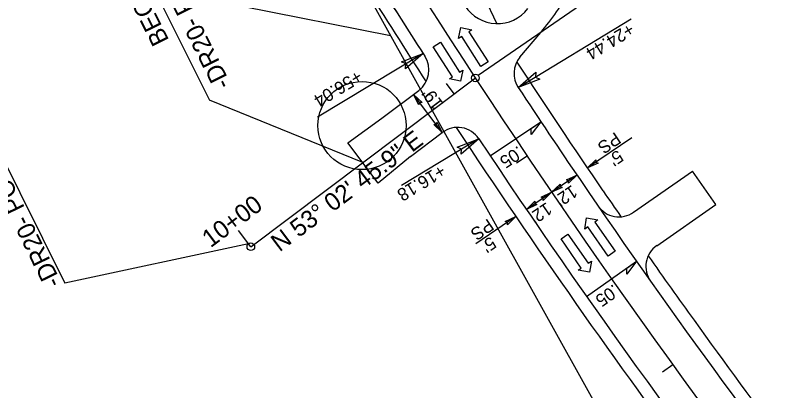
# Model space of a CAD drawing. Extents: x 472216 to 481979, y 489069 to 507339.
# Drawn here: x 476040.5 to 476343.7, y 501112.8 to 501260.2 of the extents above; entities that cross this region are included whole.
import ezdxf

# ---------------------------------------------------------------- set-up
doc = ezdxf.new("R2010")
doc.units = 0
for name, color, linetype in [('Old_Level_12', 7, 'Continuous'), ('Prop Drainage Structure Drop Inlet Grate 2 Narrow Slots and Sag Grates 840 24 CELL', 7, 'Continuous'), ('Prop Drainage Structure Drop Inlet Grate 2 Wide Slots and Sag Grates 840 22 Label', 7, 'Continuous'), ('Prop Drainage Structure Outlet Berm Ditch 850 10 CELL', 7, 'Continuous'), ('Prop Drainage Structure Pipe CSP 15in', 7, 'Continuous'), ('Prop Drainage Structure Pipe RCP 24in Class III Label', 7, 'Continuous'), ('Prop Drainage Structure Pipe Side Drain 15in Label', 7, 'Continuous'), ('Prop Erosion Embankment Toe Protection CELL', 7, 'Continuous'), ('Sheet Block Revision CELL', 7, 'Continuous'), ('Sheet North Arrow Point CELL', 7, 'Continuous'), ('Sheet PE Seal Cell', 7, 'Continuous'), ('Sheet Plan And Profile CELL', 7, 'Continuous'), ('Sheet Plot Border Outside CELL', 7, 'Continuous'), ('Sheet Profile Grid Major CELL', 7, 'Continuous'), ('Sheet Profile Grid Minor CELL', 7, 'Continuous')]:
    doc.layers.add(name, color=color, linetype=linetype)

msp = doc.modelspace()

# ---------------------------------------------------------------- linework, layer by layer
at = {"layer": 'Old_Level_12'}
for p, q in [((476055.99, 501348.9), (476116.65, 501226.92)), ((476222.19, 501236.68), (476332.17, 501312.55)), ((476002.8, 501269.83), (476059.94, 501154.92)), ((476176.9, 501202.35), (476116.65, 501226.92)), ((476132.04, 501170.48), (476059.94, 501154.92))]:
    msp.add_line(p, q, dxfattribs=at)
for centre in [(476221.13, 501235.62), (476221.13, 501235.62), (476132.94, 501169.28), (476132.94, 501169.28)]:
    msp.add_circle(centre, 1.5, dxfattribs=at)
at = {"layer": 'Prop Drainage Structure Drop Inlet Grate 2 Narrow Slots and Sag Grates 840 24 CELL'}
for points in [[(476246.9, 501218.37), (476243.02, 501213.38), (476243.05, 501215.8)], [(476284.42, 501163.56), (476280.66, 501158.47), (476280.63, 501160.9)]]:
    msp.add_lwpolyline(points, close=True, dxfattribs=at)
at = {"layer": 'Prop Drainage Structure Drop Inlet Grate 2 Wide Slots and Sag Grates 840 22 Label'}
for p, q in [((476226.94, 501205.04), (476246.9, 501218.37)), ((476264.77, 501149.77), (476284.42, 501163.56))]:
    msp.add_line(p, q, dxfattribs=at)
at = {"layer": 'Prop Drainage Structure Outlet Berm Ditch 850 10 CELL'}
for points in [[(476192.08, 501241.9), (476200.58, 501245.25), (476193.67, 501239.19), (476193.83, 501241.15)], [(476246.45, 501235.2), (476237.95, 501231.85), (476244.86, 501237.92), (476244.7, 501235.95)], [(476198.93, 501225.08), (476196.84, 501229.14), (476200.2, 501226.01), (476199.22, 501225.99)], [(476206.05, 501218.23), (476208.14, 501214.17), (476204.77, 501217.3), (476205.76, 501217.32)], [(476214, 501208.37), (476222.5, 501211.72), (476215.59, 501205.65), (476215.74, 501207.62)], [(476269.3, 501202.13), (476265.15, 501200.24), (476268.44, 501203.45), (476268.41, 501202.46)], [(476256.86, 501195.54), (476261.01, 501197.43), (476257.72, 501194.22), (476257.75, 501195.2)], [(476255.25, 501192.57), (476251.09, 501190.68), (476254.38, 501193.88), (476254.36, 501192.9)], [(476246.93, 501188.78), (476251.09, 501190.68), (476247.8, 501187.47), (476247.82, 501188.45)], [(476245.33, 501185.82), (476241.17, 501183.92), (476244.46, 501187.13), (476244.44, 501186.15)], [(476232.88, 501179.22), (476237.04, 501181.11), (476233.74, 501177.9), (476233.77, 501178.89)]]:
    msp.add_lwpolyline(points, close=True, dxfattribs=at)
at = {"layer": 'Prop Drainage Structure Pipe RCP 24in Class III Label'}
for p, q in [((476238.65, 501243.8), (476246.81, 501253.49)), ((476184.39, 501219.75), (476198.93, 501230.72)), ((476171.1, 501210.06), (476184.39, 501219.75)), ((476171.1, 501210.06), (476184.39, 501219.75)), ((476195.69, 501204.77), (476208.14, 501214.17)), ((476182.93, 501194.32), (476171.1, 501210.06)), ((476182.93, 501194.32), (476171.1, 501210.06)), ((476195.69, 501204.77), (476182.93, 501194.32)), ((476195.69, 501204.77), (476182.93, 501194.32)), ((476283.23, 501182.83), (476306.44, 501199.01)), ((476315.61, 501185.91), (476306.44, 501199.01)), ((476292.38, 501169.7), (476315.61, 501185.91))]:
    msp.add_line(p, q, dxfattribs=at)
for centre, radius, start, end in [((478615.62, 502799.59), 2872, 211.17405, 212.79272), ((478615.62, 502799.59), 2872, 211.17405, 212.77227), ((476159.25, 501327.21), 114.46, 319.9042, 330.1189), ((476229.78, 501271.96), 15, 212.6311, 322.6937), ((476192.9, 501238.7), 10, 307.047, 32.7927), ((476246.3, 501237.36), 10, 139.9042, 213.3993), ((478615.62, 502799.59), 2848, 213.3993, 214.27621), ((476214.16, 501206.19), 10, 33.565, 127.047), ((478615.62, 502799.59), 2872, 213.56501, 218.19209), ((478615.62, 502799.59), 2848, 214.27621, 218.19003), ((476277.51, 501191.03), 10, 214.5271, 304.8905), ((476298.1, 501161.5), 10, 124.8905, 215.2539)]:
    msp.add_arc(centre, radius, start, end, dxfattribs=at)
at = {"layer": 'Prop Drainage Structure Pipe Side Drain 15in Label'}
for p, q in [((476214.5, 501251.1), (476215.4, 501255.43)), ((476215.4, 501255.43), (476219.79, 501254.52)), ((476219.79, 501254.52), (476218.53, 501253.7)), ((476218.53, 501253.7), (476226.11, 501241.93)), ((476215.76, 501251.92), (476214.5, 501251.1)), ((476223.34, 501240.15), (476215.76, 501251.92)), ((476204.6, 501247.83), (476207.37, 501249.62)), ((476212.18, 501236.06), (476204.6, 501247.83)), ((476207.37, 501249.62), (476214.95, 501237.85)), ((476226.11, 501241.93), (476223.34, 501240.15)), ((476214.95, 501237.85), (476216.21, 501238.66)), ((476216.21, 501238.66), (476215.31, 501234.34)), ((476210.92, 501235.25), (476212.18, 501236.06)), ((476215.31, 501234.34), (476210.92, 501235.25)), ((476264.09, 501176.25), (476264.84, 501180.61)), ((476264.84, 501180.61), (476269.27, 501179.84)), ((476269.27, 501179.84), (476268.03, 501178.99)), ((476268.03, 501178.99), (476276, 501167.48)), ((476265.32, 501177.11), (476264.09, 501176.25)), ((476273.29, 501165.6), (476265.32, 501177.11)), ((476254.77, 501172.4), (476257.48, 501174.28)), ((476262.74, 501160.89), (476254.77, 501172.4)), ((476257.48, 501174.28), (476265.45, 501162.77)), ((476276, 501167.48), (476273.29, 501165.6)), ((476265.45, 501162.77), (476266.69, 501163.62)), ((476266.69, 501163.62), (476265.93, 501159.27)), ((476261.51, 501160.03), (476262.74, 501160.89)), ((476265.93, 501159.27), (476261.51, 501160.03))]:
    msp.add_line(p, q, dxfattribs=at)
at = {"layer": 'Prop Erosion Embankment Toe Protection CELL'}
msp.add_line((476229.61, 501256.96), (476221.93, 501273.09), dxfattribs=at)
for radius, start, end in [(2877, 211.17527, 212.96504), (2843, 213.22461, 214.45089), (2877, 213.39269, 216.72711), (2843, 214.45232, 214.70178), (2843, 215.07921, 215.7047), (2843, 215.7047, 218.19003)]:
    msp.add_arc((478615.62, 502799.59), radius, start, end, dxfattribs=at)
at = {"layer": 'Sheet Block Revision CELL'}
for p, q in [((476237.95, 501231.85), (476282.35, 501258.81)), ((476200.58, 501245.25), (476159.1, 501220.16)), ((476208.14, 501214.17), (476196.84, 501229.14)), ((476222.56, 501211.78), (476192.06, 501193.32)), ((476282.54, 501212.07), (476265.15, 501200.24)), ((476261.01, 501197.43), (476241.17, 501183.92)), ((476237.04, 501181.11), (476221.33, 501170.42))]:
    msp.add_line(p, q, dxfattribs=at)
at = {"layer": 'Sheet North Arrow Point CELL'}
for p, q in [((476280.62, 501085.39), (475827.47, 501900.81)), ((476132.94, 501169.28), (476221.13, 501235.62))]:
    msp.add_line(p, q, dxfattribs=at)
msp.add_arc((478615.62, 502799.59), 2860, 203.81642, 228.24762, dxfattribs=at)
at = {"layer": 'Sheet PE Seal Cell'}
for p, q in [((476212.86, 501229.4), (476209.85, 501233.39)), ((476212.86, 501229.4), (476209.85, 501233.39)), ((476241.47, 501204.91), (476237.32, 501202.12)), ((476298.67, 501122.89), (476294.62, 501119.96))]:
    msp.add_line(p, q, dxfattribs=at)
at = {"layer": 'Sheet Plot Border Outside CELL'}
msp.add_circle((476176.61, 501216.92), 17.32, dxfattribs=at)
at = {"layer": 'Sheet Profile Grid Major CELL'}
msp.add_line((476129.51, 501263.83), (476187.84, 501252.35), dxfattribs=at)
at = {"layer": 'Sheet Profile Grid Minor CELL'}
msp.add_line((476132.94, 501169.28), (476128.14, 501175.68), dxfattribs=at)
msp.add_line((476132.94, 501169.28), (476128.14, 501175.68), dxfattribs=at)

# ---------------------------------------------------------------- texts
at = {"layer": 'Old_Level_12'}
for s, rotation, p in [('BEGIN CONSTRUCTION', 116.4783, (476100.96, 501250.45)), ('-DR20- POT Sta.  10+55.00', 116.4783, (476125.24, 501233.12)), ('-DR20- POT Sta.  10+00.00', 116.1598, (476058.7, 501155.15))]:
    msp.add_text(s, height=7, rotation=rotation, dxfattribs=at).set_placement(p)
at = {"layer": 'Prop Drainage Structure Drop Inlet Grate 2 Narrow Slots and Sag Grates 840 24 CELL'}
for rotation, p in [(213.7249, (476237.93, 501209.12)), (215.0612, (476275.39, 501154.74))]:
    msp.add_text('.05', height=5, rotation=rotation, dxfattribs=at).set_placement(p)
at = {"layer": 'Prop Drainage Structure Pipe CSP 15in'}
for s, rotation, p in [('+24.44', 211.24, (476281.66, 501257.42)), ('+56.04', 211.24, (476174.79, 501238.89)), ("19'", 127.047, (476208.96, 501225.37)), ('PS', 214.233, (476276.06, 501214.59)), ("5'", 214.233, (476277.02, 501207.58)), ('+16.18', 211.24, (476207.55, 501201.84)), ("12'", 214.233, (476259.05, 501193.77)), ("12'", 214.233, (476249.07, 501186.98)), ('PS', 214.233, (476226.14, 501180.55)), ("5'", 214.233, (476227.1, 501173.54))]:
    msp.add_text(s, height=5, rotation=rotation, dxfattribs=at).set_placement(p)
at = {"layer": 'Sheet Plan And Profile CELL'}
msp.add_text('N 53%%d 02\' 45.9" E', height=7, rotation=36.9539, dxfattribs=at).set_placement((476144.22, 501167.03))
at = {"layer": 'Sheet Profile Grid Major CELL'}
msp.add_text('10+00', height=7, rotation=36.9539, dxfattribs=at).set_placement((476117.14, 501168.65))

doc.saveas('drawing.dxf')
